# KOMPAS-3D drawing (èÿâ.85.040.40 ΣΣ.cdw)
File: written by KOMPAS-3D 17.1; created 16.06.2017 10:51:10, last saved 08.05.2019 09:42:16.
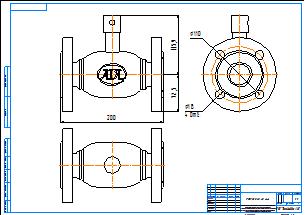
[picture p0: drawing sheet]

Sheet 1: A2, landscape

Title block, sheet 1: name: КШГ.85.040.40 фф; material: Внимание! Данный продукт является объектом авторского права ООО «Торговый Дом АДЛ». / Запрещается изменение, копирование, распространение / (в том числе путем копирования на другие сайты и ресурсы в Интернете) / или любое иное использование информации и объектов без предварительного / согласия правообладателя (ООО «Торговый Дом АДЛ»).; scale: 1:1; sheets: 1; organisation: ООО "Торговый дом АДЛ"; sheet format: A2; stored path: C:\Users\tra\Desktop\2д чертежи\Шаровые краны БИВАЛ\КШ_Бивал_серия_82_85\KOMPAS 2D\КШГ.85.040.40 фф.cdw

Views: Спереди 1, Проекционный вид 2, Проекционный вид 3
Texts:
  Klimkovich
  ADL
Dimensions and other numbers on the sheet: 200; 115,9; 72,5; 110; 18; 4 Отв.; 1:1; 1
